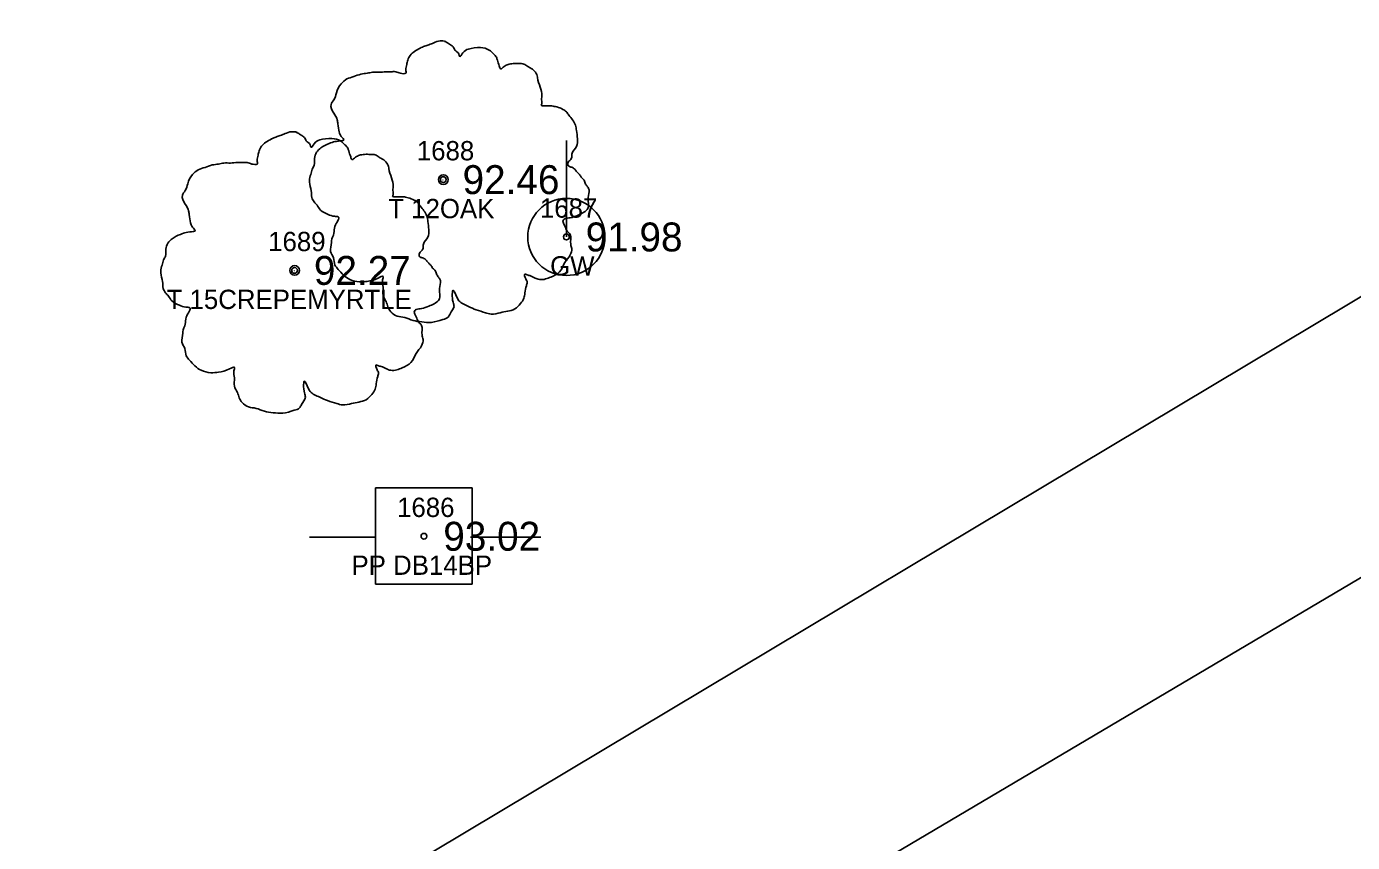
# Model space of a CAD drawing. Extents: x 2529517 to 2532038, y 935000 to 936944.
# Drawn here: x 2530965.7 to 2531034.4, y 935894.6 to 935936.9 of the extents above; entities that cross this region are included whole.
import ezdxf

# ---------------------------------------------------------------- set-up
doc = ezdxf.new("R2010")
doc.units = 0
for name, color, linetype in [('Default', 7, 'Continuous'), ('RD_EX_Road', 7, 'Continuous'), ('RD_EX_TX_UT_ELEV', 7, 'Continuous'), ('RD_EX_TX_VEG_ELEV', 7, 'Continuous'), ('RD_EX_UT', 7, 'Continuous'), ('RD_EX_UT_txCode', 7, 'Continuous'), ('RD_EX_VEG', 7, 'Continuous'), ('RD_EX_VEG_txCode', 7, 'Continuous'), ('RD_HC_Cl', 7, 'Continuous'), ('RD_HC_Survey_ELEV', 7, 'Continuous'), ('RD_SMD_Locator', 7, 'Continuous')]:
    doc.layers.add(name, color=color, linetype=linetype)

msp = doc.modelspace()

# ---------------------------------------------------------------- linework, layer by layer
at = {"layer": 'Default'}
msp.add_line((2530557.048, 935625.341), (2531768.068, 936342.554), dxfattribs=at)
at = {"layer": 'RD_EX_Road'}
msp.add_lwpolyline([(2530213.129, 935600.159), (2530313.796, 935600.808), (2530414.146, 935601.135), (2530426.724, 935601.431), (2530429.462, 935603.551), (2530467.667, 935608.622), (2530486.463, 935612.382), (2530518.022, 935622.553), (2530522.163, 935623.679), (2530567.909, 935646.012), (2530609.299, 935670.154), (2530695.461, 935720.024), (2530775.853, 935769.269), (2530868.285, 935824.026), (2530924.837, 935856.951), (2530956.207, 935875.821), (2531040.717, 935926.378), (2531079.452, 935947.762)], dxfattribs=at)
at = {"layer": 'RD_EX_UT'}
for p, q in [((2530993.71, 935925.985), (2530993.71, 935930.985)), ((2530988.822, 935912.974), (2530983.822, 935912.974)), ((2530983.822, 935912.974), (2530983.822, 935907.974)), ((2530988.822, 935907.974), (2530988.822, 935912.974)), ((2530980.391, 935910.411), (2530983.86, 935910.411)), ((2530988.75, 935910.411), (2530992.391, 935910.411)), ((2530983.822, 935907.974), (2530988.822, 935907.974))]:
    msp.add_line(p, q, dxfattribs=at)
msp.add_circle((2530993.71, 935925.985), 1.999, dxfattribs=at)
at = {"layer": 'RD_EX_VEG'}
for centre, radius in [((2530987.331, 935928.958), 0.25), ((2530987.318, 935928.94), 0.0001), ((2530979.627, 935924.25), 0.25), ((2530979.614, 935924.231), 0.0001)]:
    msp.add_circle(centre, radius, dxfattribs=at)
for points in [[(2530987.463, 935936.126), (2530987.163, 935936.151), (2530986.838, 935936.051), (2530986.588, 935935.951), (2530986.363, 935935.876), (2530986.138, 935935.776), (2530985.838, 935935.601), (2530985.613, 935935.401), (2530985.488, 935935.151), (2530985.438, 935934.926), (2530985.388, 935934.651), (2530985.388, 935934.476), (2530985.264, 935934.451), (2530985.114, 935934.476), (2530984.864, 935934.551), (2530984.614, 935934.551), (2530984.364, 935934.551), (2530984.014, 935934.526), (2530983.664, 935934.526), (2530983.389, 935934.476), (2530983.064, 935934.426), (2530982.69, 935934.301), (2530982.34, 935934.176), (2530982.04, 935933.927), (2530981.79, 935933.452), (2530981.665, 935933.102), (2530981.515, 935932.852), (2530981.665, 935932.402), (2530981.84, 935932.052), (2530981.865, 935931.852), (2530981.94, 935931.428), (2530982.04, 935931.203), (2530982.165, 935931.003), (2530982.09, 935930.978), (2530981.715, 935930.928), (2530981.415, 935930.828), (2530980.99, 935930.603), (2530980.765, 935930.378), (2530980.665, 935930.053), (2530980.641, 935929.703), (2530980.541, 935929.504), (2530980.466, 935929.229), (2530980.441, 935929.154), (2530980.391, 935928.829), (2530980.491, 935928.379), (2530980.516, 935928.029), (2530980.641, 935927.804), (2530980.79, 935927.629), (2530980.965, 935927.379), (2530981.365, 935927.155), (2530981.69, 935927.055), (2530981.89, 935927.03), (2530981.715, 935926.53), (2530981.665, 935926.18), (2530981.54, 935925.78), (2530981.54, 935925.705), (2530981.49, 935925.23), (2530981.64, 935924.905), (2530981.715, 935924.531), (2530981.89, 935924.306), (2530982.165, 935924.006), (2530982.49, 935923.781), (2530982.99, 935923.656), (2530983.389, 935923.681), (2530983.964, 935923.856), (2530984.214, 935923.931), (2530984.189, 935923.756), (2530984.214, 935923.381), (2530984.214, 935922.956), (2530984.364, 935922.632), (2530984.464, 935922.357), (2530984.614, 935922.107), (2530984.939, 935921.882), (2530985.338, 935921.807), (2530985.763, 935921.657), (2530986.213, 935921.582), (2530986.713, 935921.557), (2530987.313, 935921.707), (2530987.587, 935921.832), (2530987.687, 935922.007), (2530987.887, 935922.382), (2530987.837, 935922.607), (2530987.862, 935923.206), (2530987.962, 935923.031), (2530988.137, 935922.681), (2530988.637, 935922.382), (2530989.037, 935922.207), (2530989.512, 935922.057), (2530989.812, 935921.982), (2530990.286, 935922.057), (2530990.661, 935922.132), (2530991.036, 935922.257), (2530991.336, 935922.532), (2530991.511, 935922.806), (2530991.561, 935923.081), (2530991.636, 935923.456), (2530991.686, 935923.631)], [(2530991.686, 935923.631), (2530991.611, 935923.806), (2530991.561, 935924.056), (2530991.636, 935924.031), (2530991.811, 935923.981), (2530992.086, 935923.856), (2530992.31, 935923.781), (2530992.635, 935923.806), (2530992.91, 935923.906), (2530993.36, 935924.181), (2530993.635, 935924.656), (2530993.91, 935925.055), (2530993.985, 935925.38), (2530993.935, 935925.605), (2530993.91, 935926.105), (2530993.71, 935926.355), (2530993.66, 935926.48), (2530993.56, 935926.88), (2530993.635, 935926.93), (2530993.91, 935926.98), (2530994.285, 935927.105), (2530994.559, 935927.229), (2530994.784, 935927.404), (2530994.859, 935927.629), (2530994.834, 935928.029), (2530994.884, 935928.429), (2530994.809, 935928.579), (2530994.709, 935928.729), (2530994.634, 935928.929), (2530994.484, 935929.079), (2530994.385, 935929.229), (2530994.285, 935929.329), (2530994.16, 935929.479), (2530993.985, 935929.603), (2530993.835, 935929.653), (2530993.785, 935929.803), (2530993.935, 935930.003), (2530993.985, 935930.103), (2530994.01, 935930.328), (2530994.235, 935930.678), (2530994.285, 935931.078), (2530994.235, 935931.503), (2530994.185, 935931.778), (2530994.035, 935932.052), (2530993.835, 935932.302), (2530993.71, 935932.477), (2530993.535, 935932.602), (2530993.21, 935932.727), (2530992.96, 935932.777), (2530992.61, 935932.777), (2530992.41, 935932.827), (2530992.435, 935932.877), (2530992.435, 935933.027), (2530992.435, 935933.302), (2530992.36, 935933.752), (2530992.21, 935934.251), (2530992.21, 935934.276), (2530992.11, 935934.526), (2530991.886, 935934.726), (2530991.711, 935934.826), (2530991.511, 935934.951), (2530991.261, 935934.976), (2530990.961, 935934.976), (2530990.686, 935934.926), (2530990.486, 935934.826), (2530990.311, 935934.701), (2530990.236, 935934.851), (2530990.136, 935935.151), (2530990.086, 935935.301), (2530989.936, 935935.476), (2530989.712, 935935.676), (2530989.262, 935935.801), (2530988.637, 935935.726), (2530988.337, 935935.526), (2530988.187, 935935.351), (2530988.137, 935935.476), (2530987.937, 935935.676), (2530987.837, 935935.851), (2530987.662, 935935.976), (2530987.513, 935936.076), (2530987.413, 935936.126)], [(2530979.759, 935931.417), (2530979.459, 935931.442), (2530979.134, 935931.342), (2530978.884, 935931.242), (2530978.659, 935931.167), (2530978.434, 935931.067), (2530978.134, 935930.892), (2530977.909, 935930.692), (2530977.784, 935930.443), (2530977.734, 935930.218), (2530977.685, 935929.943), (2530977.685, 935929.768), (2530977.56, 935929.743), (2530977.41, 935929.768), (2530977.16, 935929.843), (2530976.91, 935929.843), (2530976.66, 935929.843), (2530976.31, 935929.818), (2530975.96, 935929.818), (2530975.685, 935929.768), (2530975.361, 935929.718), (2530974.986, 935929.593), (2530974.636, 935929.468), (2530974.336, 935929.218), (2530974.086, 935928.743), (2530973.961, 935928.393), (2530973.811, 935928.144), (2530973.961, 935927.694), (2530974.136, 935927.344), (2530974.161, 935927.144), (2530974.236, 935926.719), (2530974.336, 935926.494), (2530974.461, 935926.294), (2530974.386, 935926.269), (2530974.011, 935926.219), (2530973.711, 935926.119), (2530973.286, 935925.895), (2530973.062, 935925.67), (2530972.962, 935925.345), (2530972.937, 935924.995), (2530972.837, 935924.795), (2530972.762, 935924.52), (2530972.737, 935924.445), (2530972.687, 935924.12), (2530972.787, 935923.67), (2530972.812, 935923.321), (2530972.937, 935923.096), (2530973.087, 935922.921), (2530973.261, 935922.671), (2530973.661, 935922.446), (2530973.986, 935922.346), (2530974.186, 935922.321), (2530974.011, 935921.821), (2530973.961, 935921.471), (2530973.836, 935921.072), (2530973.836, 935920.997), (2530973.786, 935920.522), (2530973.936, 935920.197), (2530974.011, 935919.822), (2530974.186, 935919.597), (2530974.461, 935919.297), (2530974.786, 935919.073), (2530975.286, 935918.948), (2530975.685, 935918.973), (2530976.26, 935919.147), (2530976.51, 935919.222), (2530976.485, 935919.048), (2530976.51, 935918.673), (2530976.51, 935918.248), (2530976.66, 935917.923), (2530976.76, 935917.648), (2530976.91, 935917.398), (2530977.235, 935917.173), (2530977.635, 935917.098), (2530978.059, 935916.948), (2530978.509, 935916.873), (2530979.009, 935916.848), (2530979.609, 935916.998), (2530979.884, 935917.123), (2530979.984, 935917.298), (2530980.183, 935917.673), (2530980.133, 935917.898), (2530980.158, 935918.498), (2530980.258, 935918.323), (2530980.433, 935917.973), (2530980.933, 935917.673), (2530981.333, 935917.498), (2530981.808, 935917.348), (2530982.108, 935917.273), (2530982.582, 935917.348), (2530982.957, 935917.423), (2530983.332, 935917.548), (2530983.632, 935917.823), (2530983.807, 935918.098), (2530983.857, 935918.373), (2530983.932, 935918.748), (2530983.982, 935918.923)], [(2530983.982, 935918.923), (2530983.907, 935919.098), (2530983.857, 935919.347), (2530983.932, 935919.322), (2530984.107, 935919.272), (2530984.382, 935919.147), (2530984.607, 935919.073), (2530984.931, 935919.098), (2530985.206, 935919.197), (2530985.656, 935919.472), (2530985.931, 935919.947), (2530986.206, 935920.347), (2530986.281, 935920.672), (2530986.231, 935920.897), (2530986.206, 935921.396), (2530986.006, 935921.646), (2530985.956, 935921.771), (2530985.856, 935922.171), (2530985.931, 935922.221), (2530986.206, 935922.271), (2530986.581, 935922.396), (2530986.856, 935922.521), (2530987.08, 935922.696), (2530987.155, 935922.921), (2530987.13, 935923.321), (2530987.18, 935923.72), (2530987.105, 935923.87), (2530987.005, 935924.02), (2530986.93, 935924.22), (2530986.781, 935924.37), (2530986.681, 935924.52), (2530986.581, 935924.62), (2530986.456, 935924.77), (2530986.281, 935924.895), (2530986.131, 935924.945), (2530986.081, 935925.095), (2530986.231, 935925.295), (2530986.281, 935925.395), (2530986.306, 935925.62), (2530986.531, 935925.969), (2530986.581, 935926.369), (2530986.531, 935926.794), (2530986.481, 935927.069), (2530986.331, 935927.344), (2530986.131, 935927.594), (2530986.006, 935927.769), (2530985.831, 935927.894), (2530985.506, 935928.019), (2530985.256, 935928.069), (2530984.906, 935928.069), (2530984.706, 935928.119), (2530984.731, 935928.169), (2530984.731, 935928.318), (2530984.731, 935928.593), (2530984.656, 935929.043), (2530984.507, 935929.543), (2530984.507, 935929.568), (2530984.407, 935929.818), (2530984.182, 935930.018), (2530984.007, 935930.118), (2530983.807, 935930.243), (2530983.557, 935930.268), (2530983.257, 935930.268), (2530982.982, 935930.218), (2530982.782, 935930.118), (2530982.607, 935929.993), (2530982.532, 935930.143), (2530982.432, 935930.443), (2530982.382, 935930.592), (2530982.233, 935930.767), (2530982.008, 935930.967), (2530981.558, 935931.092), (2530980.933, 935931.017), (2530980.633, 935930.817), (2530980.483, 935930.642), (2530980.433, 935930.767), (2530980.233, 935930.967), (2530980.133, 935931.142), (2530979.959, 935931.267), (2530979.809, 935931.367), (2530979.709, 935931.417)]]:
    msp.add_spline(points, degree=3, dxfattribs=at)
at = {"layer": 'RD_HC_Cl'}
msp.add_line((2530557.048, 935625.341), (2531768.068, 936342.554), dxfattribs=at)
at = {"layer": 'RD_SMD_Locator'}
for centre in [(2530987.331, 935928.958), (2530993.71, 935925.985), (2530979.627, 935924.25), (2530986.331, 935910.465)]:
    msp.add_circle(centre, 0.15, dxfattribs=at)

# ---------------------------------------------------------------- texts
at = {"layer": 'RD_EX_TX_UT_ELEV'}
msp.add_text('91.98', height=1.5, dxfattribs=at).set_placement((2530994.71, 935925.235))
at = {"layer": 'RD_EX_TX_VEG_ELEV'}
for s, p in [('92.46', (2530988.331, 935928.208)), ('92.27', (2530980.627, 935923.5))]:
    msp.add_text(s, height=1.5, dxfattribs=at).set_placement(p)
at = {"layer": 'RD_EX_UT_txCode'}
for s, p in [('1687', (2530992.34, 935926.985)), ('GW', (2530992.868, 935923.985)), ('1686', (2530984.937, 935911.465)), ('PP DB14BP', (2530982.575, 935908.465))]:
    msp.add_text(s, height=1, dxfattribs=at).set_placement(p)
at = {"layer": 'RD_EX_VEG_txCode'}
for s, p in [('1688', (2530985.961, 935929.958)), ('T 12OAK', (2530984.48, 935926.958)), ('1689', (2530978.257, 935925.25)), ('T 15CREPEMYRTLE', (2530972.993, 935922.25))]:
    msp.add_text(s, height=1, dxfattribs=at).set_placement(p)
at = {"layer": 'RD_HC_Survey_ELEV'}
msp.add_text('93.02', height=1.5, dxfattribs=at).set_placement((2530987.331, 935909.715))

doc.saveas('drawing.dxf')
